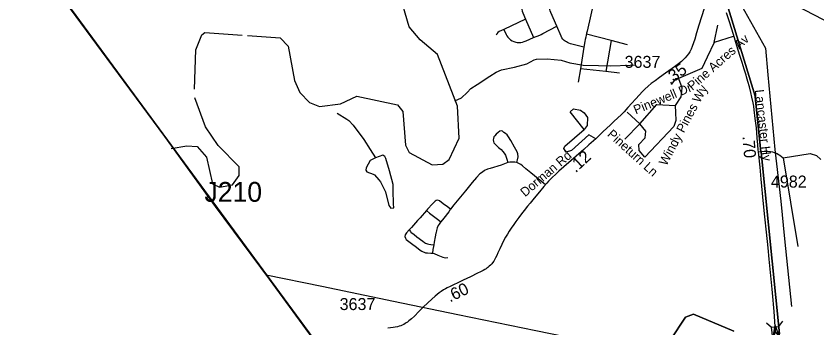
# Model space of a CAD drawing. Extents: x 1383679 to 1536984, y 460658 to 651027.
# Drawn here: x 1430469 to 1438807, y 483158 to 486408 of the extents above; entities that cross this region are included whole.
import ezdxf

# ---------------------------------------------------------------- set-up
doc = ezdxf.new("R2010")
doc.units = 0
for name, color, linetype in [('Default', 7, 'Continuous'), ('Exist Boundary Political City Limit New', 7, 'Continuous'), ('Exist Boundary Political StateLine', 7, 'Continuous'), ('Exist Hydrographic Creek Single Shore', 7, 'Continuous'), ('Exist Hydrographic Misc Water Feature', 7, 'Continuous'), ('Exist Road Non-System Structure Non-Sys Other Number Label', 7, 'Continuous'), ('Exist Road Non-System Type 51', 7, 'Continuous'), ('Exist Road Non-System Type 51 Label', 7, 'Continuous'), ('Exist Road Secondary Mileage Hundredths English Label', 7, 'Continuous'), ('Exist Road Secondary Structure Standard Bridge Attributed CELL', 7, 'Continuous'), ('Exist Road Secondary Structure Standard Bridge CELL', 7, 'Continuous'), ('Exist Road Secondary Type 51 Attributed', 7, 'Continuous'), ('Exist Road Secondary Type 51 Label', 7, 'Continuous'), ('Exist Road Secondary Type 51 Number Label', 7, 'Continuous'), ('Exist Utilities Electrical Transmission Line', 7, 'Continuous'), ('Map Preparation Boundary City Limit Buffer Line', 7, 'Continuous')]:
    doc.layers.add(name, color=color, linetype=linetype)

msp = doc.modelspace()

# ---------------------------------------------------------------- linework, layer by layer
at = {"layer": 'Default'}
for p, q in [((1438163.1, 485571.3), (1437873, 486526)), ((1432181.8, 484932.8), (1432153, 484971.6))]:
    msp.add_line(p, q, dxfattribs=at)
msp.add_lwpolyline([(1438418.1, 483095.9), (1438225.1, 484987.8), (1438224.5, 484994.1), (1438164.4, 485565.1), (1438163.1, 485571.3)], dxfattribs=at)
at = {"layer": 'Exist Boundary Political City Limit New'}
for p, q in [((1438163.1, 485571.3), (1437873, 486526)), ((1437873, 486526), (1438163.1, 485571.3))]:
    msp.add_line(p, q, dxfattribs=at)
for points in [[(1435952, 479801.4), (1430224.2, 487598.4), (1429553.8, 488500.4), (1429482.6, 488597.1), (1429128, 489084.7), (1429069.5, 489168.1), (1428883.5, 489419.4), (1428415.9, 490057.6), (1427841.6, 490835.3), (1427277, 491601), (1426753.6, 492315.7), (1426163.9, 493129.8), (1425843, 493564.7)], [(1438418.1, 483095.9), (1438225.1, 484987.8), (1438224.5, 484994.1), (1438164.4, 485565.1), (1438163.1, 485571.3)], [(1438163.1, 485571.3), (1438164.4, 485565.1), (1438224.5, 484994.1), (1438225.1, 484987.8), (1438418.1, 483095.9)], [(1437942.2, 483125.5), (1437523.1, 483302.2), (1437439.1, 483271), (1437284.1, 483034.5)]]:
    msp.add_lwpolyline(points, dxfattribs=at)
at = {"layer": 'Exist Boundary Political StateLine'}
msp.add_lwpolyline([(1434317.4, 482010.1), (1433106.8, 483665.1), (1432544.2, 484422.6), (1432016.8, 485151.6), (1431419.3, 485963.8), (1430819.6, 486778), (1430224.2, 487598.4), (1429653.9, 488361.6), (1429028.9, 489221), (1428415.9, 490057.6), (1427841.7, 490835.3), (1427277, 491601), (1426753.6, 492315.7), (1426163.9, 493129.8), (1425558.5, 493950.3), (1425002, 494713.7), (1424515.4, 495379.8), (1424015.2, 496066), (1423493.9, 496786.9), (1422865.4, 497651.7), (1422145.1, 498628.5)], dxfattribs=at)
at = {"layer": 'Exist Hydrographic Creek Single Shore'}
for points in [[(1432879, 486206.1), (1433219.1, 486182.1), (1433301.1, 486095.1), (1433369.1, 485736), (1433425.2, 485610.1), (1433523.1, 485506.4), (1433630.1, 485464.9), (1433847.2, 485493.3), (1434016.1, 485571.9), (1434439.2, 485481.4), (1434496.2, 485414.6), (1434523.1, 485062.8), (1434563.1, 484986.5), (1434802.1, 484857), (1434911.1, 484864.7), (1434978.1, 484912.5), (1435083.1, 485136.9), (1435064.2, 485468.8), (1434858.2, 486008), (1434678.1, 486159.3), (1434563.1, 486296.2), (1434470.1, 486606.6)], [(1432325.8, 485644.2), (1432341.2, 486055.3), (1432402.2, 486211.6), (1432436.1, 486237.2), (1432824.2, 486209.9)], [(1432083.5, 485027.4), (1432246.1, 485056.1), (1432355.1, 485047.4), (1432453.1, 484937.1), (1432514.1, 484660.1), (1432588.1, 484625.8), (1432722.1, 484649.4), (1432791.1, 484746.5), (1432793.1, 484838.3), (1432572.1, 485059.4), (1432442.1, 485252.4), (1432329.7, 485555.4)], [(1437284.1, 483034.5), (1437439.2, 483271), (1437523.1, 483302.2), (1437942.3, 483125.5)]]:
    msp.add_lwpolyline(points, dxfattribs=at)
at = {"layer": 'Exist Hydrographic Misc Water Feature'}
for points in [[(1435037.7, 485522.7), (1435106.4, 485555.7), (1435165.6, 485612), (1435202.4, 485651.5), (1435271.3, 485696), (1435403, 485782), (1435467.8, 485824.2), (1435524.3, 485847.7), (1435656.9, 485874.6), (1435785.7, 485908.1), (1435864.5, 485950.8), (1435888.7, 485958.5), (1435998.8, 485962), (1436142.7, 485949.3), (1436234.1, 485919.6), (1436277.9, 485912.9), (1436371.7, 485897.1), (1436531.6, 485891.4), (1436657.7, 485889.7), (1436861.9, 485895.4), (1436916, 485900.1)], [(1433810.7, 485394.7), (1433913.6, 485334.4), (1433935.3, 485318.3), (1433980.3, 485269), (1434089.6, 485120.8), (1434157.4, 485016), (1434209.8, 484930.4)], [(1434209.8, 484930.4), (1434155.3, 484903.6), (1434113.8, 484826.5), (1434109.3, 484802.8), (1434120.9, 484784.5), (1434186.5, 484761.1), (1434200.4, 484752.6), (1434247.4, 484701.6), (1434265, 484681.5), (1434317, 484576.3), (1434350.2, 484433.6), (1434371.7, 484406.9), (1434401.8, 484408.8), (1434400.6, 484452.3), (1434397.1, 484588.6), (1434396.5, 484652.6), (1434357.3, 484793.7), (1434317.8, 484924.1), (1434308.2, 484944.8), (1434286.4, 484959.2), (1434209.8, 484930.4)]]:
    msp.add_lwpolyline(points, dxfattribs=at)
at = {"layer": 'Exist Road Non-System Type 51'}
for p, q in [((1435773.9, 486374.4), (1435549.1, 486268.2)), ((1435773.9, 486374.4), (1435857.1, 486182.2)), ((1436663.9, 486152.8), (1436407.1, 486218.2)), ((1436663.9, 486152.8), (1436610.4, 485828.6)), ((1436835.1, 486109.2), (1436663.9, 486152.8)), ((1436381.9, 486084.4), (1436345.4, 485858.3)), ((1436345.4, 485858.3), (1436322.9, 485720.2)), ((1436610.4, 485828.6), (1436345.4, 485858.3)), ((1436751.8, 485812.8), (1436610.4, 485828.6)), ((1438453.9, 484929.1), (1438606.5, 484005.5))]:
    msp.add_line(p, q, dxfattribs=at)
for points in [[(1435681.1, 486809.6), (1435712.1, 486741.8), (1435717.8, 486728.4), (1435721.1, 486715), (1435723.4, 486700.5), (1435725.6, 486683.8), (1435726.6, 486662.6), (1435731.1, 486509.8), (1435732.2, 486493.1), (1435733.4, 486477.5), (1435737.9, 486459.7), (1435745.6, 486439.6), (1435773.9, 486374.4)], [(1436098.5, 486302.3), (1436036.8, 486444), (1436030, 486461.1), (1436025.8, 486477.2), (1436023.1, 486493.4), (1436023.1, 486507.9), (1436024.9, 486524.9), (1436038.5, 486665.3)], [(1439489.3, 486049.5), (1438332.3, 486653.7)], [(1436491.4, 486593.7), (1436414.2, 486249.8), (1436409.4, 486228.2), (1436407.1, 486218.2)], [(1435857.1, 486182.2), (1435920.8, 486208.9), (1435935.6, 486216), (1435952.6, 486224.5), (1436098.5, 486302.3)], [(1436381.9, 486084.4), (1436243, 486117.7), (1436225.1, 486123.6), (1436210.6, 486130.4), (1436198.6, 486137.2), (1436185.9, 486145.8), (1436174.9, 486154.2), (1436162.9, 486167.1), (1436152.6, 486181.6), (1436143.4, 486199.4), (1436098.5, 486302.3)], [(1437935.7, 486195.7), (1437735.9, 486133.2), (1437776.5, 486311.3)], [(1435549.1, 486268.2), (1435548.2, 486267.8), (1435500.4, 486245.6), (1435485.9, 486235.5), (1435474.6, 486221), (1435466.9, 486208.8)], [(1435549.1, 486268.2), (1435571.6, 486214.6), (1435580.1, 486199.7), (1435590, 486186.9), (1435603.5, 486172.8), (1435618.4, 486160.8), (1435633.9, 486150.8), (1435651.6, 486142.3), (1435670.8, 486135.2), (1435687.8, 486131.7), (1435705.4, 486130.2), (1435723.1, 486131.7), (1435740.9, 486134.5), (1435758.6, 486140.9), (1435780.5, 486150.1), (1435857.1, 486182.2)], [(1436407.1, 486218.2), (1436404.6, 486207.8), (1436399.9, 486187.3), (1436395, 486164.5), (1436391.4, 486142.9), (1436381.9, 486084.4)], [(1437735.9, 486133.2), (1437664.1, 485980.2), (1437607.9, 485861.4), (1437367.5, 485755.2), (1437401.8, 485664.6), (1437398.7, 485620.9), (1437389.3, 485564.7), (1437330, 485474.1), (1437333.1, 485402.2), (1437339.4, 485321), (1437317.5, 485258.5), (1437014.7, 484936.8), (1436955.4, 485005.5), (1436952.3, 485068), (1437017.8, 485139.8), (1437024.1, 485208.6), (1436961.6, 485283.5), (1436805.5, 485124.2)], [(1437367.5, 485755.2), (1437336.3, 485752.1), (1437289.4, 485692.8)], [(1436961.6, 485283.5), (1437139.6, 485486.6), (1437330, 485474.1)], [(1436506.2, 485129), (1436430.9, 485171.1), (1436252.9, 485005.5), (1436196.7, 484989.9), (1436171.7, 485027.4), (1436184.2, 485052.4), (1436384, 485224.2), (1436237.3, 485408.5), (1436271.7, 485439.7), (1436346.6, 485427.2), (1436384, 485399.1), (1436418.4, 485352.3), (1436415.3, 485267.9), (1436384, 485224.2)], [(1436961.6, 485283.5), (1436830.5, 485405.4)], [(1435682.6, 484882.3), (1435690.6, 484910.2), (1435695.9, 484942.2), (1435694.6, 484972.7), (1435686.6, 484992.6), (1435657.4, 485043.1), (1435621.6, 485109.5), (1435597.6, 485148), (1435583.1, 485169.2), (1435564.5, 485185.2), (1435548.5, 485195.8), (1435533.2, 485207.5), (1435518.1, 485211.2), (1435504.6, 485206.8), (1435487.4, 485194.7), (1435466.2, 485176.6), (1435452.6, 485160.8), (1435443.6, 485148), (1435439.1, 485133), (1435437.6, 485116.4), (1435438.4, 485101.3), (1435444.4, 485087.8), (1435456.4, 485071.2), (1435493.4, 485038.1), (1435518.1, 485016.3), (1435536.2, 484996.8), (1435552, 484978.7), (1435563.4, 484958.3), (1435577.6, 484916.2), (1435589.6, 484880.8)], [(1438198.4, 484992.4), (1438257.3, 484998.8), (1438275.4, 484999.3), (1438297.2, 484999.3), (1438322.8, 484996.3), (1438344.7, 484991.9), (1438363.5, 484986.6), (1438380.9, 484979.6), (1438391.5, 484975.1), (1438406.6, 484966.7), (1438420.3, 484957), (1438453.9, 484929.1)], [(1438453.9, 484929.1), (1438737.1, 484976.8), (1438802.4, 484955.7), (1438845.9, 484913.4)], [(1435589.6, 484880.8), (1435518.9, 484855.2), (1435405.2, 484819.8), (1435375.9, 484810.8), (1435347.4, 484798), (1435324, 484782.2), (1435296.9, 484762.7), (1435263.8, 484727.2), (1435218.6, 484672.3), (1435147.9, 484585), (1435078.6, 484502.2), (1435026.6, 484440.5), (1434990.9, 484397)], [(1435682.6, 484882.3), (1435663.4, 484884.6), (1435637.9, 484884.6), (1435611.5, 484883.8), (1435589.6, 484880.8)], [(1435980.6, 484650.2), (1435904.4, 484711), (1435828.8, 484773.5), (1435776.9, 484817.2), (1435742.4, 484846.5), (1435723.6, 484860.5), (1435704.9, 484871), (1435682.6, 484882.3)], [(1434990.9, 484397), (1434960.9, 484419.3), (1434915.9, 484451.2), (1434877.4, 484481.6), (1434860.1, 484490.9), (1434843, 484486.9), (1434832.4, 484480.3), (1434805.9, 484452.5), (1434754.1, 484394.2), (1434742.2, 484380.6)], [(1434742.2, 484380.6), (1434676, 484305.4), (1434650.2, 484276.2), (1434585.9, 484203.3), (1434561.5, 484179)], [(1434742.2, 484380.6), (1434775.1, 484355.5), (1434872.5, 484281.8), (1434892.8, 484265.3)], [(1434990.9, 484397), (1434989.9, 484393.8), (1434973.5, 484367.2), (1434921.2, 484301.2), (1434892.8, 484265.3)], [(1434892.8, 484265.3), (1434887.8, 484259.2), (1434874.9, 484240.2), (1434865.5, 484224.8), (1434855.1, 484201.7), (1434846.6, 484175.1), (1434841.5, 484152.8), (1434840.1, 484145.4), (1434832.9, 484106.5), (1434822.8, 484052), (1434817.5, 484024.2)], [(1434561.5, 484179), (1434532.9, 484150.3), (1434519.6, 484129.2), (1434518, 484111), (1434522.2, 484094.8), (1434532.1, 484081), (1434546.2, 484069.3), (1434587.1, 484037.7), (1434637.9, 483999.3), (1434676.2, 483969.3), (1434694.6, 483957.7), (1434706.5, 483951.5), (1434719.1, 483946.1), (1434732.8, 483942), (1434753.8, 483939.3), (1434786.2, 483938.5), (1434797, 483938.4), (1434804.9, 483937.2)], [(1434561.5, 484179), (1434574.8, 484163.4), (1434580.6, 484156.3), (1434614.4, 484130.8), (1434642.9, 484109), (1434705.6, 484061), (1434722.9, 484048.2), (1434732.9, 484042.7), (1434743, 484037.8), (1434753, 484034.3), (1434768.1, 484031.3), (1434788, 484028.4), (1434817.5, 484024.2)], [(1434817.5, 484024.2), (1434814, 484005.2), (1434809.5, 483976.2), (1434804.9, 483937.2)], [(1434804.9, 483937.2), (1434807.1, 483936.8), (1434822.9, 483932.7), (1434861.2, 483916.8), (1434911.2, 483895.2), (1434935.4, 483890.2), (1434965.4, 483891.8)]]:
    msp.add_lwpolyline(points, dxfattribs=at)
at = {"layer": 'Exist Road Secondary Structure Standard Bridge Attributed CELL'}
msp.add_lwpolyline([(1438351, 483062.9), (1438371.2, 483183.2), (1438413.8, 483068.9), (1438377, 483122.5)], close=True, dxfattribs=at)
at = {"layer": 'Exist Road Secondary Structure Standard Bridge CELL'}
for p, q in [((1438282.6, 483211.5), (1438335.7, 483167.5)), ((1438450, 483227.4), (1438406, 483174.2))]:
    msp.add_line(p, q, dxfattribs=at)
msp.add_lwpolyline([(1438406, 483174.2), (1438420.3, 483023.8), (1438350, 483017.1), (1438335.7, 483167.5)], close=True, dxfattribs=at)
at = {"layer": 'Exist Road Secondary Type 51 Attributed'}
for points in [[(1437661.7, 486576.2), (1437579.2, 486312), (1437554.1, 486231.8), (1437534.5, 486167.3), (1437521.7, 486127.2), (1437508.2, 486090), (1437496, 486061.9), (1437482.5, 486035), (1437470.3, 486014.5), (1437454, 485991.7), (1437436.9, 485971.5), (1437419, 485953.2), (1437396.7, 485932.7), (1437367.4, 485908.8), (1437339.1, 485888.3), (1437301.6, 485861.5), (1437229.9, 485811.1), (1437167.9, 485766.9), (1437121.7, 485733.8), (1437081.6, 485703.5), (1437050.7, 485677.6), (1437014.9, 485644.5), (1436986.6, 485617.2), (1436959.3, 485587.4), (1436918.6, 485541.8), (1436881.7, 485500.5), (1436838.2, 485453.1), (1436799.7, 485411), (1436768.7, 485379.7), (1436735.2, 485348), (1436694.3, 485308.9), (1436653.7, 485271.5)], [(1438377, 483122.5), (1438362.3, 483328.1), (1438343.5, 483523.3), (1438339.9, 483561), (1438309.9, 483875.8), (1438298, 483993.4), (1438282.5, 484157), (1438265.4, 484316.1), (1438251.7, 484452.6), (1438227.1, 484708), (1438216, 484832.3), (1438198.4, 484992.4), (1438196.1, 485013.2), (1438192.1, 485066), (1438186.4, 485139.3), (1438176.4, 485242), (1438165.6, 485339.5), (1438154.2, 485431.7), (1438148.6, 485467.6), (1438142.5, 485502.9), (1438130.1, 485561.9), (1438118.1, 485611.2), (1438104.4, 485670.4), (1438089.1, 485725.1), (1438075, 485772.8), (1438069.3, 485792.2), (1438050.4, 485855.2), (1438029.2, 485922.5), (1438005.5, 485997.8), (1437973.5, 486098.1), (1437938, 486214), (1437895.9, 486348.8), (1437866, 486441)], [(1436653.7, 485271.5), (1436583, 485205.8), (1436506.2, 485129), (1436431.4, 485066), (1436379.7, 485018.3), (1436301.8, 484946.2), (1436121.7, 484791.2), (1436087.3, 484760.6), (1436050.5, 484726.2), (1436033.5, 484708.9), (1436013.2, 484687.1), (1435994.4, 484666.3), (1435963.9, 484631), (1435917.4, 484575.2), (1435881.2, 484531.7), (1435850.1, 484494.6), (1435821.4, 484459.8), (1435794, 484425.9), (1435760.7, 484383.5), (1435732.7, 484347.3), (1435704.2, 484309.9), (1435674, 484268.1), (1435650.2, 484235.1), (1435625.4, 484199.2), (1435603.4, 484166.7), (1435584.7, 484136.9), (1435564.9, 484102.5), (1435548.9, 484074.3), (1435526.7, 484028.2), (1435505.8, 483982.5), (1435485.9, 483940.8), (1435473.2, 483914.4), (1435461.2, 483889.7), (1435449.9, 483868.1), (1435442.3, 483855), (1435431.1, 483838.2), (1435421.3, 483826.5), (1435409.3, 483813.9), (1435395.3, 483800.6), (1435381.4, 483789.3), (1435370.8, 483781.6), (1435361.9, 483775.8), (1435348.4, 483767.3), (1435330.7, 483757.5), (1435303.3, 483743.6), (1435274, 483728.3), (1435199.7, 483692.5), (1435125.1, 483656.6), (1435067.3, 483628.8), (1435022.6, 483607.7), (1434989.3, 483591.6), (1434959.1, 483576.9), (1434939.5, 483566.7), (1434918.9, 483555.2), (1434895.1, 483539.5), (1434873.5, 483523), (1434833, 483490.4), (1434760.1, 483424.3), (1434704.8, 483370), (1434664.3, 483329.7), (1434616.4, 483282.4), (1434586.9, 483255), (1434559.9, 483231.8), (1434544.3, 483219.6), (1434532.1, 483210.8), (1434519.8, 483203.1), (1434505.3, 483194.6), (1434490.3, 483187.2), (1434476.8, 483181.8), (1434459.3, 483175.7), (1434441, 483170.7), (1434417.8, 483165.5), (1434394.9, 483161.8), (1434367.4, 483158.8), (1434340.8, 483157)]]:
    msp.add_lwpolyline(points, dxfattribs=at)
at = {"layer": 'Exist Utilities Electrical Transmission Line'}
for points in [[(1437088.2, 488040.6), (1437130.3, 487657.6), (1437467.7, 487293.2), (1437686.2, 487032.9), (1437778.2, 486897.1), (1437958.3, 486633.1), (1438272.6, 486071.6), (1438295.6, 485794.6), (1438368.5, 485017.3), (1438429.8, 484480), (1438468.1, 484085.8), (1438541, 483381.1)], [(1433072.2, 483712.7), (1433651.4, 483595.3), (1434400.2, 483437.8), (1435069.4, 483299.8), (1435881.8, 483131), (1436509.1, 483004.1), (1437148.5, 482868.8), (1437781.8, 482737.8), (1438363.1, 482613.6), (1438773.3, 482521.1), (1439016.5, 482483.7), (1439560.8, 482377.7), (1440446, 482207.6), (1441293.1, 482028.1), (1442164.2, 481852.1), (1443035.6, 481682.1), (1443460.2, 481596.3), (1443946.4, 481483.5), (1444590.1, 481343.7), (1444822.1, 481229.4), (1445208.7, 481032.3), (1445379.2, 480953), (1445787.7, 480753.5), (1446059.4, 480620.6)]]:
    msp.add_lwpolyline(points, dxfattribs=at)
at = {"layer": 'Map Preparation Boundary City Limit Buffer Line'}
for p, q in [((1438163.1, 485571.3), (1437873, 486526)), ((1437873, 486526), (1438163.1, 485571.3)), ((1438163.1, 485571.3), (1437873, 486526))]:
    msp.add_line(p, q, dxfattribs=at)
for points in [[(1435952, 479801.4), (1430224.2, 487598.4), (1429553.8, 488500.4), (1429482.6, 488597.1), (1429128, 489084.7), (1429069.5, 489168.1), (1428883.5, 489419.4), (1428415.9, 490057.6), (1427841.6, 490835.3), (1427277, 491601), (1426753.6, 492315.7), (1426163.9, 493129.8), (1425843, 493564.7)], [(1438418.1, 483095.9), (1438225.1, 484987.8), (1438224.5, 484994.1), (1438164.4, 485565.1), (1438163.1, 485571.3)], [(1438163.1, 485571.3), (1438164.4, 485565.1), (1438224.5, 484994.1), (1438225.1, 484987.8), (1438418.1, 483095.9)], [(1438418.1, 483095.9), (1438225.1, 484987.8), (1438224.5, 484994.1), (1438164.4, 485565.1), (1438163.1, 485571.3)], [(1437942.2, 483125.5), (1437523.1, 483302.2), (1437439.1, 483271), (1437284.1, 483034.5)]]:
    msp.add_lwpolyline(points, dxfattribs=at)

# ---------------------------------------------------------------- texts
at = {"layer": 'Exist Road Non-System Structure Non-Sys Other Number Label'}
msp.add_text('J210', height=206.69, dxfattribs=at).set_placement((1432431.2, 484472.4))
at = {"layer": 'Exist Road Non-System Type 51 Label'}
for s, rotation, p in [('Pine Acres Av', 41.43283, (1437510.6, 485627.3)), ('Pinewell Dr', 22.51875, (1436921.2, 485381.4)), ('Windy Pines Wy', 62.11811, (1437239.6, 484840.3)), ('Pineturn Ln', 317.85604, (1436616.9, 485165.2))]:
    msp.add_text(s, height=95, rotation=rotation, dxfattribs=at).set_placement(p)
at = {"layer": 'Exist Road Secondary Mileage Hundredths English Label'}
for s, rotation, p in [('.35', 35.53746, (1437276.5, 485689)), ('.70', 274.3941, (1438032, 485155.2)), ('.12', 42.7377, (1436295.3, 484769.7)), ('.60', 25.67723, (1434986.6, 483423.3))]:
    msp.add_text(s, height=125, rotation=rotation, dxfattribs=at).set_placement(p)
at = {"layer": 'Exist Road Secondary Type 51 Label'}
for s, rotation, p in [('Lancaster Hy', 276.36869, (1438160.3, 485636.9)), ('Dorman Rd', 40.46248, (1435768.6, 484519.2))]:
    msp.add_text(s, height=95, rotation=rotation, dxfattribs=at).set_placement(p)
at = {"layer": 'Exist Road Secondary Type 51 Number Label'}
for s, p in [('3637', (1436805.1, 485867.7)), ('4982', (1438328, 484620.7)), ('3637', (1433838.2, 483344.8))]:
    msp.add_text(s, height=125, dxfattribs=at).set_placement(p)

doc.saveas('drawing.dxf')
